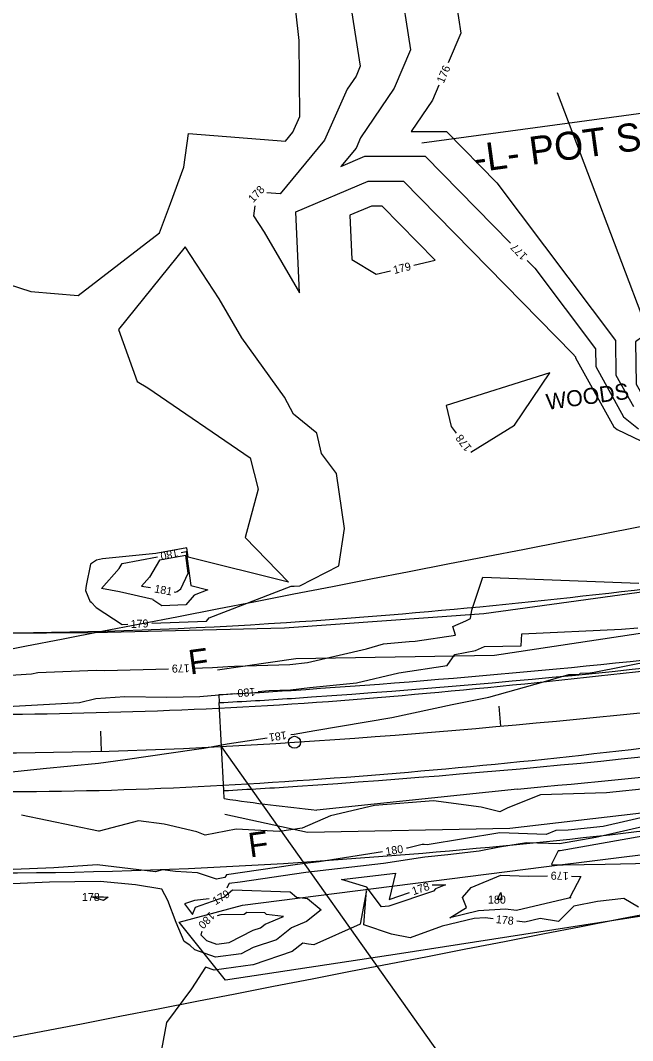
# Model space of a CAD drawing. Extents: x 2086416 to 2115205, y 575507 to 632762.
# Drawn here: x 2111202.3 to 2111355.3, y 581547.6 to 581802.4 of the extents above; entities that cross this region are included whole.
import ezdxf

# ---------------------------------------------------------------- set-up
doc = ezdxf.new("R2010")
doc.units = 0
for name, color, linetype in [('DTM Contours Major', 7, 'Continuous'), ('DTM Contours Major Text', 7, 'Continuous'), ('DTM Contours Minor', 7, 'Continuous'), ('DTM Contours Minor Text', 7, 'Continuous'), ('Exist Hydrographic FEMA Cross Section', 7, 'Continuous'), ('Exist Right of Way Line', 7, 'Continuous'), ('Exist Roads EOP', 7, 'Continuous'), ('Exist Vegetation Woods Line', 7, 'Continuous'), ('Exist Vegetation Woods Line Text', 7, 'Continuous'), ('Prop EOT', 7, 'Continuous'), ('Prop Horizontal Alignment', 7, 'Continuous'), ('Prop Horizontal Alignment Station Label', 7, 'Continuous'), ('Prop Horizontal Alignment Tick Small', 7, 'Continuous'), ('Prop Paved Shoulder', 7, 'Continuous'), ('Prop SS Fill Line', 7, 'Continuous'), ('Prop SS Fill Text', 7, 'Continuous')]:
    doc.layers.add(name, color=color, linetype=linetype)

msp = doc.modelspace()

# ---------------------------------------------------------------- linework, layer by layer
at = {"layer": 'DTM Contours Major'}
for points in [[(2111336.48, 581784.42), (2111359.19, 581724.48), (2111356.03, 581722.18), (2111356.22, 581711.58), (2111357.93, 581708.49), (2111367.42, 581700.82), (2111367.7, 581700.69), (2111370.5, 581699.17), (2111370.16, 581701.31)], [(2111237.71, 581656.19), (2111235.41, 581657.68), (2111235.53, 581657.78), (2111227.09, 581659.68), (2111222.6, 581660.49), (2111227.04, 581665.52), (2111227.77, 581666.76), (2111236.57, 581668.4)], [(2111242.47, 581669.51), (2111243.8, 581669.76), (2111244.9, 581661.29), (2111249.21, 581660.21), (2111245.74, 581658.87), (2111243.68, 581656.43), (2111237.71, 581656.19)], [(2111261.76, 581634.8), (2111264.49, 581635.02), (2111269.8, 581635.25), (2111274.63, 581635.79), (2111286.36, 581637), (2111296.9, 581639.48), (2111308.95, 581641.32), (2111310.89, 581644.07), (2111316.03, 581645.06), (2111318.27, 581646.08), (2111327.46, 581646.18), (2111327.64, 581649.21), (2111352.5, 581650.37), (2111356.59, 581650.74)], [(2111156.02, 581630.25), (2111171.53, 581630.22), (2111172.21, 581630.06), (2111193.33, 581630.76), (2111197.59, 581630.96), (2111217.1, 581632.04), (2111221.17, 581633.02), (2111228.47, 581633.56), (2111238.81, 581633.36), (2111247.18, 581633.58), (2111255.78, 581634.3)], [(2111397.68, 581607.39), (2111377.21, 581605.77), (2111373.52, 581605.22), (2111372.31, 581605.14), (2111361.36, 581604.17), (2111347.99, 581601.11), (2111339.17, 581600.17), (2111336.15, 581600.07), (2111333.7, 581599.12), (2111322.16, 581599.48), (2111304, 581596.49), (2111303.23, 581596.59), (2111302.72, 581596.56), (2111299.03, 581595.67), (2111298.77, 581595.63)], [(2111292.84, 581594.72), (2111277, 581592.28), (2111273.44, 581591.86), (2111270.44, 581591.43), (2111253.87, 581589.01), (2111253.45, 581588.31), (2111251.32, 581587.94), (2111246.59, 581589.53), (2111241.11, 581589.81), (2111237.84, 581590.23), (2111236.11, 581589.78), (2111221.5, 581591.49), (2111210.72, 581590.77), (2111200.53, 581590.34), (2111194.18, 581590.08)], [(2111321.43, 581582.81), (2111322.41, 581584.56), (2111322.63, 581582.86), (2111321.43, 581582.81)], [(2111262.32, 581575.77), (2111263.48, 581576.69), (2111268.04, 581578.57), (2111263.87, 581579.07), (2111263.39, 581579.48), (2111258.93, 581579.62), (2111258.26, 581579.06), (2111252.4, 581579.05), (2111251.52, 581578.74)], [(2111247.71, 581574.81), (2111247.39, 581574.02), (2111248.84, 581572.58), (2111251.37, 581571.72), (2111254.52, 581572.13), (2111260.53, 581575.16), (2111262.32, 581575.77)]]:
    msp.add_lwpolyline(points, dxfattribs=at)
at = {"layer": 'DTM Contours Minor'}
for points in [[(2111267.74, 581979.73), (2111268.68, 581977.35), (2111273.87, 581968.84), (2111278.26, 581965.37), (2111287.18, 581945.83), (2111288.13, 581942.79), (2111297.45, 581922.87), (2111301.36, 581904.36), (2111305.53, 581895.97), (2111311.8, 581877.57), (2111312.33, 581875.57), (2111312.59, 581874.51), (2111311.38, 581850.65), (2111314.56, 581814.31), (2111311.18, 581806.9), (2111312.39, 581799.22), (2111309.24, 581791.82)], [(2111255.12, 581935.83), (2111260.16, 581925.24), (2111262.37, 581919.63), (2111267.2, 581916.59), (2111274.77, 581907.52), (2111277.54, 581898.66), (2111284.66, 581883.15), (2111286.66, 581875.21), (2111292.46, 581863.42), (2111294.84, 581853.39), (2111294.68, 581850.26), (2111295.1, 581845.49), (2111282.89, 581818.74), (2111287.27, 581791.01), (2111286.2, 581788.48), (2111283.99, 581785.23), (2111278.31, 581772.53), (2111267.27, 581759.11), (2111263.91, 581759.38)], [(2111292.27, 581905.43), (2111295.25, 581895.93), (2111295.93, 581894.45), (2111301, 581875.36), (2111303.71, 581863.95), (2111303.03, 581850.45), (2111304.83, 581829.9), (2111297.03, 581812.82), (2111299.83, 581795.12), (2111295.74, 581785.49), (2111287.34, 581773.08), (2111286.2, 581770.54), (2111282.44, 581765.97), (2111288.39, 581768.49), (2111303.45, 581768.49), (2111324.76, 581746.78)], [(2111172.65, 581747.61), (2111175.49, 581739.43), (2111189.76, 581746.49), (2111199.26, 581736.52), (2111204.94, 581734.72), (2111216.79, 581733.74), (2111237.11, 581749.36), (2111239.88, 581756.72), (2111243.14, 581765.77), (2111244.32, 581774.22), (2111268.57, 581772.28), (2111270.42, 581774.52), (2111272.15, 581778.4), (2111272.02, 581797.41), (2111269.39, 581820.52), (2111268.74, 581824.66)], [(2111306.89, 581786.29), (2111305.27, 581782.49), (2111300, 581774.7), (2111308.81, 581774.7), (2111321.39, 581761.89), (2111351, 581722.5), (2111351.15, 581713.78), (2111355.49, 581705.96)], [(2111260.91, 581756.14), (2111260.56, 581753.66), (2111263.25, 581749.57), (2111272.06, 581734.37), (2111271.17, 581754.63), (2111289.23, 581762.28), (2111298.09, 581762.28), (2111340.41, 581719.17), (2111341.02, 581718.36), (2111341.03, 581718.18), (2111350.61, 581700.9), (2111351.45, 581700.22), (2111365.39, 581693.62), (2111366.1, 581693.23), (2111372.81, 581687.77), (2111373.33, 581687.33), (2111373.12, 581686.65), (2111370.29, 581684.39), (2111374.42, 581679.53), (2111381.41, 581682.41)], [(2111292.74, 581756.06), (2111290.08, 581756.06), (2111284.68, 581753.78), (2111285.16, 581742.69), (2111291.22, 581739.02), (2111294.81, 581739.88)], [(2111300.64, 581741.29), (2111305.98, 581742.58), (2111292.74, 581756.06)], [(2111252.01, 581732.92), (2111243.5, 581745.85), (2111226.88, 581725.22), (2111231.48, 581712.27), (2111234.2, 581710.64), (2111259.76, 581693.18), (2111261.75, 581685.36), (2111258.49, 581673.26), (2111269.36, 581662.09), (2111244.24, 581668.39), (2111243.94, 581670.7), (2111236.21, 581669.26), (2111222.87, 581667.9), (2111221.36, 581667.61), (2111219.89, 581666.65), (2111218.75, 581661.3), (2111218.6, 581660), (2111219.79, 581657.23), (2111220.12, 581657.16), (2111220.04, 581657.09), (2111221.26, 581655.77), (2111227.78, 581651.56), (2111229.17, 581651.62)], [(2111328.97, 581742.5), (2111330.9, 581740.53), (2111346.01, 581720.43), (2111346.09, 581715.98), (2111353.05, 581703.43), (2111356.77, 581700.42)], [(2111235.16, 581651.86), (2111248.8, 581652.41), (2111249.48, 581653.23), (2111270, 581661.14), (2111270.74, 581661.11), (2111272.17, 581661.2), (2111281.87, 581666.23), (2111283.35, 581675.5), (2111281.36, 581689.25), (2111277.59, 581694.27), (2111276.39, 581699.32), (2111270.55, 581704.07), (2111268.32, 581708.33), (2111257.68, 581723.13), (2111252.01, 581732.92)], [(2111334.62, 581714.44), (2111308.74, 581706.23), (2111309.97, 581701), (2111311.25, 581699.31)], [(2111314.86, 581694.57), (2111325.77, 581701.36), (2111334.62, 581714.44)], [(2111243.66, 581668.81), (2111237.11, 581667.58), (2111234.59, 581663.33), (2111232.64, 581661.13), (2111234.82, 581660.74)], [(2111240.73, 581659.67), (2111241.12, 581659.6), (2111241.51, 581659.76), (2111242.4, 581660.43), (2111244.24, 581664.37), (2111243.66, 581668.81)], [(2111245.37, 581640.64), (2111250.37, 581640.77), (2111254.13, 581641.08), (2111255.87, 581641.16), (2111269.65, 581641.57), (2111274.1, 581642.03), (2111288.83, 581645.5), (2111293.03, 581646.75), (2111299.5, 581647.25), (2111300.99, 581647.37), (2111311.02, 581648.91), (2111310.41, 581651.07), (2111313.6, 581652.46), (2111314.81, 581653.01), (2111315.14, 581655.09), (2111317.9, 581663.35), (2111356.87, 581661.83)], [(2111269.92, 581624.06), (2111270.71, 581624.17), (2111275.89, 581625.03), (2111295.14, 581628.3), (2111310.24, 581631.56), (2111319.39, 581633.41), (2111333.07, 581637.24), (2111339.35, 581639.05), (2111342.16, 581639.08), (2111342.18, 581639.38), (2111344.6, 581639.49), (2111345.71, 581639.59), (2111368.06, 581644.02), (2111371.03, 581644.96), (2111390.01, 581648.91), (2111399.54, 581651.29), (2111412.87, 581655.54), (2111414.88, 581656.76), (2111417.77, 581657.24), (2111425.19, 581659.11), (2111446.75, 581659.06), (2111455.96, 581661.78), (2111465.02, 581661.96)], [(2111040.21, 581649), (2111046.47, 581648.46), (2111049.91, 581648.03), (2111050.75, 581647.88), (2111057.54, 581647.61), (2111075.81, 581645.03), (2111083.62, 581643.07), (2111103.56, 581640.9), (2111112.25, 581640.07), (2111123.96, 581638.8), (2111133.06, 581638.34), (2111152.19, 581638), (2111160.29, 581638.04), (2111171.77, 581637.82), (2111172.14, 581637.73), (2111178.61, 581637.94), (2111201.19, 581638.98), (2111205.15, 581639.2), (2111206.66, 581639.57), (2111221.28, 581640.1), (2111223.41, 581640.06), (2111239.38, 581640.48)], [(2111065.66, 581626.31), (2111071.03, 581625.45), (2111073.38, 581624.88), (2111091.16, 581621.7), (2111097.77, 581620.24), (2111111.15, 581618.17), (2111122.33, 581616.26), (2111132.45, 581615.38), (2111147.13, 581613.63), (2111164.79, 581613.17), (2111172.03, 581613.12), (2111180.86, 581613.52), (2111196.96, 581614.4), (2111208.07, 581615.53), (2111221.82, 581616.87), (2111228.5, 581617.81), (2111246.33, 581620.36), (2111248.16, 581620.66), (2111254.01, 581621.76), (2111263.98, 581623.2)], [(2111360.01, 581610.67), (2111348.79, 581609.46), (2111332.31, 581608.96), (2111324.1, 581605.76), (2111322.14, 581604.75), (2111317.5, 581605.9), (2111305.55, 581607.48), (2111290.82, 581606.36), (2111279.83, 581603.73), (2111272.71, 581600.66), (2111267.06, 581599.84), (2111256.22, 581600.43), (2111248.5, 581598.95), (2111246.39, 581599.77), (2111238.28, 581601.67), (2111231.86, 581602.49), (2111222.02, 581599.89), (2111221.95, 581599.9), (2111221.84, 581599.89), (2111202.6, 581603.92)], [(2111362.09, 581601.98), (2111346.11, 581598.33), (2111337.08, 581596.74), (2111328.76, 581597.04), (2111322.03, 581595.92), (2111316.94, 581594.92), (2111309.15, 581594.01), (2111303.4, 581593.42), (2111293.1, 581591.83), (2111273.64, 581589.57), (2111257.28, 581587.2), (2111254.52, 581586.8), (2111254.12, 581586.13), (2111253.96, 581585.7)], [(2111357.86, 581598.66), (2111337.18, 581595.02), (2111337.09, 581595.03), (2111336.74, 581594.97), (2111335.14, 581591.87), (2111335.07, 581591.57), (2111336.54, 581591.51), (2111336.87, 581591.52), (2111337.94, 581591.48), (2111348.47, 581591.69), (2111359.85, 581591.92)], [(2111288.92, 581585.89), (2111282.55, 581587.85), (2111296.07, 581589.43), (2111294.45, 581582.83), (2111299.54, 581584.6)], [(2111316.8, 581580.01), (2111309.62, 581578.3), (2111313.78, 581580.85), (2111312.79, 581583.33), (2111315.01, 581585.85), (2111322.39, 581588.9), (2111329.17, 581588.65), (2111334.04, 581588.72)], [(2111249.53, 581583.04), (2111245.81, 581582.57), (2111243.32, 581581.76), (2111245.36, 581579.12), (2111246.09, 581580.93), (2111253.15, 581583.42), (2111253.2, 581583.42), (2111255.36, 581585.24), (2111269.76, 581584.79), (2111271.3, 581583.45), (2111274.05, 581583.12), (2111277.51, 581580.25), (2111273.86, 581577.34), (2111270.05, 581575.77), (2111266.29, 581572.81), (2111260.51, 581570.84), (2111257.48, 581569.31), (2111251.06, 581568.48), (2111245.89, 581570.23), (2111244.7, 581571.41), (2111243.24, 581572.39), (2111241.23, 581577.06), (2111239.21, 581582.59), (2111237.68, 581585.4), (2111231.09, 581586.48), (2111222.25, 581587.38), (2111209.61, 581587.17), (2111200.47, 581586.79)], [(2111305.21, 581586.53), (2111308.57, 581586.52), (2111306.06, 581585.48), (2111305.58, 581584.94), (2111294.43, 581581.22), (2111292.6, 581581.05), (2111289.26, 581585.4), (2111288.92, 581585.89)], [(2111340.04, 581588.66), (2111342.41, 581588.57), (2111339.65, 581583.38), (2111339.87, 581583.3), (2111339.48, 581583.22), (2111339.44, 581583.18), (2111339.38, 581583.19), (2111326.3, 581580.11), (2111323.57, 581580.4), (2111316.8, 581580.01)], [(2111320.44, 581578.03), (2111318.46, 581578.24), (2111315.74, 581578.08), (2111307.71, 581576.17), (2111299.75, 581573.25), (2111295.09, 581574.15), (2111288.19, 581576.48), (2111288.82, 581585.08), (2111287.21, 581576.68), (2111275.7, 581571.5), (2111274.31, 581571.68), (2111272.9, 581571.92), (2111270.27, 581569.85), (2111260.49, 581566.51), (2111260.44, 581566.49), (2111250.75, 581565.23), (2111248.56, 581565.97), (2111245.06, 581560.52), (2111238.88, 581552.13), (2111236.15, 581537.73), (2111257.66, 581504.04), (2111292.42, 581515.32)], [(2111219.99, 581583.47), (2111223.08, 581583.52), (2111224.29, 581583.4), (2111223.13, 581582.56), (2111219.99, 581583.47)], [(2111356.74, 581580.89), (2111353.12, 581583.13), (2111346.53, 581582.32), (2111340.61, 581581.19), (2111336.82, 581577.33), (2111332.22, 581578.09), (2111328.39, 581577.19), (2111326.41, 581577.4)]]:
    msp.add_lwpolyline(points, dxfattribs=at)
at = {"layer": 'Exist Hydrographic FEMA Cross Section'}
for points in [[(2111357.16, 581675.91), (2111347.55, 581674.04), (2111337.94, 581672.17), (2111328.33, 581670.31), (2111318.72, 581668.44), (2111309.12, 581666.57), (2111299.51, 581664.7), (2111289.9, 581662.83), (2111280.3, 581660.96), (2111270.69, 581659.1), (2111261.08, 581657.23), (2111251.47, 581655.36), (2111241.86, 581653.49), (2111232.26, 581651.62), (2111222.65, 581649.76), (2111213.04, 581647.89), (2111203.43, 581646.02), (2111193.83, 581644.15)], [(2111361.7, 581579.76), (2111352.09, 581577.89), (2111342.48, 581576.02), (2111332.87, 581574.15), (2111323.27, 581572.29), (2111313.66, 581570.42), (2111304.05, 581568.55), (2111294.44, 581566.69), (2111284.84, 581564.82), (2111275.23, 581562.95), (2111265.62, 581561.08), (2111256.02, 581559.21), (2111246.41, 581557.34), (2111236.8, 581555.48), (2111227.19, 581553.61), (2111217.58, 581551.74), (2111207.98, 581549.87), (2111198.37, 581548)]]:
    msp.add_lwpolyline(points, dxfattribs=at)
at = {"layer": 'Exist Right of Way Line'}
for centre, radius, start, end in [((2111158.41, 583306.56), 1658.19, 273.81807, 277.39391), ((2111190.81, 582821.14), 1171.69, 266.74835, 273.81807), ((2111158.41, 583306.56), 1718.19, 273.81807, 277.39391), ((2111190.81, 582821.14), 1231.69, 266.74835, 273.81807)]:
    msp.add_arc(centre, radius, start, end, dxfattribs=at)
at = {"layer": 'Exist Roads EOP'}
for points in [[(2110977.48, 581650.48), (2111025.79, 581641.84), (2111074.55, 581635.25), (2111123.2, 581631.18), (2111172.22, 581629.18), (2111221.29, 581629.52), (2111270.17, 581631.7), (2111319.13, 581635.84), (2111368.33, 581641.12), (2111417.78, 581647.42)], [(2110973.54, 581631.44), (2111022.55, 581622.76), (2111072.45, 581615.95), (2111122.07, 581611.59), (2111171.98, 581610.01), (2111221.99, 581610.11), (2111271.48, 581612.54), (2111320.96, 581616.67), (2111370.32, 581622.18), (2111419.52, 581628.55)]]:
    msp.add_spline(points, degree=3, dxfattribs=at)
at = {"layer": 'Exist Vegetation Woods Line'}
for points in [[(2111452.1, 581736.22), (2111479.27, 581697.5), (2111499.68, 581677.78), (2111492.04, 581671.34), (2111416.64, 581665.13), (2111367.28, 581660.93), (2111318.17, 581654.2), (2111268.32, 581650.61), (2111220.66, 581649.45), (2111173.29, 581649.12), (2111125.98, 581651.57), (2111078.27, 581655.72), (2111059.79, 581657.65)], [(2111257.87, 581581.4), (2111333.1, 581590.97), (2111406.18, 581600.07), (2111473.94, 581614.42), (2111501.63, 581613.42), (2111525.04, 581604.65), (2111555.79, 581590.73), (2111597.41, 581531.02), (2111635.4, 581485.12), (2111692.38, 581438.81), (2111736.92, 581397.7), (2111757.96, 581379.06)], [(2111566.76, 581548.29), (2111551.99, 581576.31), (2111385.4, 581583.05), (2111297.09, 581569.27), (2111253.55, 581562.72), (2111242.01, 581577.17), (2111257.87, 581581.4)]]:
    msp.add_lwpolyline(points, dxfattribs=at)
at = {"layer": 'Prop EOT'}
msp.add_line((2111253.15, 581610.05), (2111252.02, 581632.03), dxfattribs=at)
for centre, radius, start, end in [((2111114.87, 583958.95), 2331.03, 273.81807, 277.77101), ((2111190.81, 582821.14), 1190.69, 272.94666, 273.81807), ((2111114.87, 583958.95), 2353.03, 273.81807, 277.77101), ((2111190.81, 582821.14), 1212.69, 272.94666, 273.81807)]:
    msp.add_arc(centre, radius, start, end, dxfattribs=at)
at = {"layer": 'Prop Horizontal Alignment'}
for centre, radius, start, end in [((2111114.87, 583958.95), 2342.03, 273.81807, 277.77101), ((2111190.81, 582821.14), 1201.69, 266.74835, 273.81807)]:
    msp.add_arc(centre, radius, start, end, dxfattribs=at)
at = {"layer": 'Prop Horizontal Alignment Station Label'}
for p, q in [((2111302.64, 581771.83), (2111433.3, 581789.66)), ((2111329.83, 581512.18), (2111252.58, 581621.04))]:
    msp.add_line(p, q, dxfattribs=at)
msp.add_circle((2111270.83, 581622.12), 1.5, dxfattribs=at)
at = {"layer": 'Prop Horizontal Alignment Tick Small'}
for p, q in [((2111322.39, 581626.13), (2111321.95, 581631.11)), ((2111222.6, 581619.87), (2111222.47, 581624.87))]:
    msp.add_line(p, q, dxfattribs=at)
at = {"layer": 'Prop Paved Shoulder'}
for p, q in [((2111251.91, 581634.02), (2111252.02, 581632.03)), ((2111253.25, 581608.06), (2111253.15, 581610.05)), ((2111326.54, 581610.44), (2111276.44, 581605.17))]:
    msp.add_line(p, q, dxfattribs=at)
for centre, radius, start, end in [((2111114.87, 583958.95), 2329.03, 273.81807, 276.73016), ((2111190.81, 582821.14), 1188.69, 272.94666, 273.81807), ((2111114.87, 583958.95), 2358.03, 275.14998, 277.77101), ((2111329.05, 582121.56), 519.07, 261.6024, 264.1826)]:
    msp.add_arc(centre, radius, start, end, dxfattribs=at)
at = {"layer": 'Prop SS Fill Line'}
for p, q in [((2111320.81, 581643.91), (2111369.91, 581651.29)), ((2111251.59, 581640.22), (2111271.14, 581643.05)), ((2111271.14, 581643.05), (2111320.81, 581643.91)), ((2111253.45, 581604.18), (2111274.07, 581599.66)), ((2111324.66, 581600.66), (2111374.86, 581606.53)), ((2111274.07, 581599.66), (2111324.66, 581600.66))]:
    msp.add_line(p, q, dxfattribs=at)

# ---------------------------------------------------------------- texts
at = {"layer": 'DTM Contours Major Text'}
for rotation, p in [(190.6014, (2111241.57, 581670.36)), (184.7504, (2111260.95, 581635.73)), (8.7618, (2111293.71, 581593.84)), (225.884, (2111249.71, 581579.92))]:
    msp.add_text('180', height=2, rotation=rotation, dxfattribs=at).set_placement(p)
msp.add_text('180', height=2, dxfattribs=at).set_placement((2111319.16, 581581.81))
at = {"layer": 'DTM Contours Minor Text'}
for s, rotation, p in [('176', 66.9548, (2111308.1, 581786.57)), ('178', 47.1916, (2111260.51, 581756.77)), ('177', 134.4764, (2111329.17, 581743.72)), ('179', 13.5775, (2111295.75, 581739.08)), ('178', 127.3439, (2111315.22, 581695.71)), ('181', 349.7816, (2111235.69, 581659.56)), ('179', 2.3195, (2111229.93, 581650.65)), ('179', 181.5027, (2111244.62, 581641.62)), ('181', 188.2286, (2111268.72, 581624.9)), ('179', 179.3827, (2111339.33, 581589.74)), ('178', 18.7578, (2111300.54, 581583.91)), ('179', 31.0551, (2111251.08, 581581.38)), ('178', 354.0126, (2111321.06, 581576.96))]:
    msp.add_text(s, height=2, rotation=rotation, dxfattribs=at).set_placement(p)
msp.add_text('178', height=2, dxfattribs=at).set_placement((2111217.72, 581582.47))
at = {"layer": 'Exist Vegetation Woods Line Text'}
msp.add_text('WOODS', height=4, rotation=7.771, dxfattribs=at).set_placement((2111333.99, 581705.13))
at = {"layer": 'Prop Horizontal Alignment Station Label'}
msp.add_text('-L- POT Sta. 13+81 +/-  ', height=7, rotation=7.771, dxfattribs=at).set_placement((2111316.09, 581764.43))
at = {"layer": 'Prop SS Fill Text'}
for p in [(2111244.77, 581639.03), (2111259.71, 581593.32)]:
    msp.add_text('F', height=6.1, rotation=7.771, dxfattribs=at).set_placement(p)

doc.saveas('drawing.dxf')
